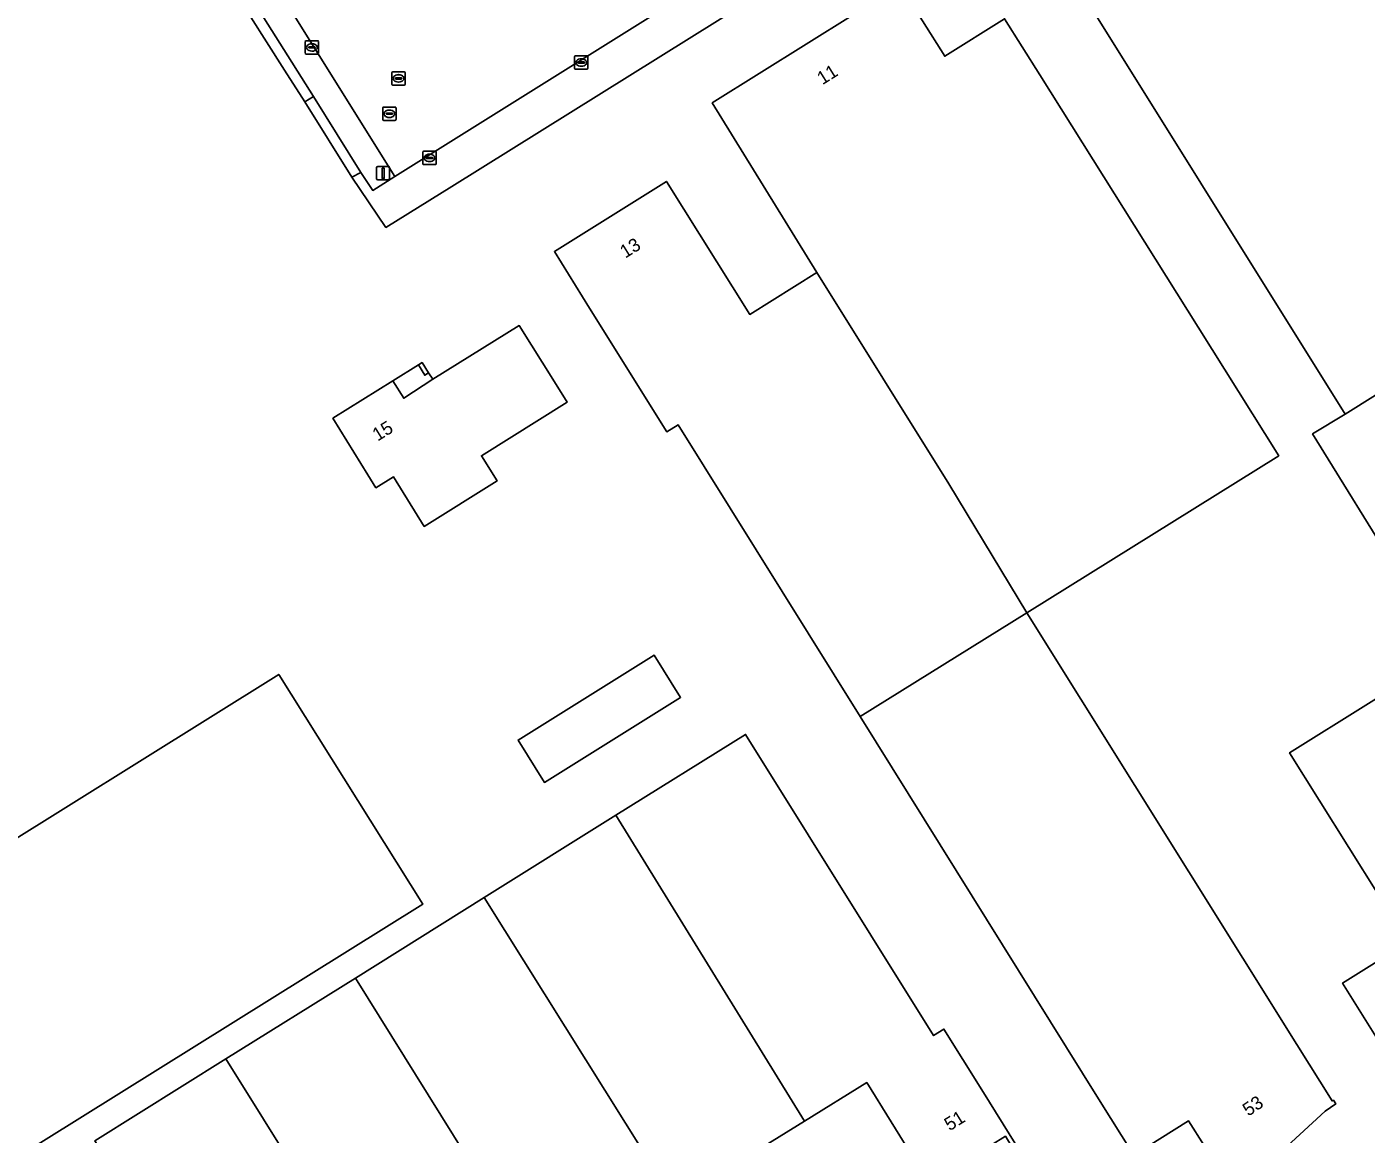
# Model space of a CAD drawing. Extents: x 158455 to 159797, y 387218 to 388672.
# Drawn here: x 158762.6 to 158863.3, y 387547.3 to 387630.6 of the extents above; entities that cross this region are included whole.
import ezdxf

# ---------------------------------------------------------------- set-up
doc = ezdxf.new("R2010")
doc.units = 0
for name, color, linetype in [('IMGEO_Erf', 7, 'Continuous'), ('IMGEO_Kolk', 7, 'Continuous'), ('IMGEO_Lichtmast', 7, 'Continuous'), ('IMGEO_Pand', 7, 'Continuous'), ('IMGEO_Pand_nummerreeks', 7, 'Continuous'), ('IMGEO_Pand_overbouw', 7, 'Continuous'), ('IMGEO_Parkeervlak_open', 7, 'Continuous'), ('IMGEO_Rijbaan_lokaal_gesloten', 7, 'Continuous'), ('IMGEO_Rioolput', 7, 'Continuous'), ('IMGEO_Voetpad_open', 7, 'Continuous')]:
    doc.layers.add(name, color=color, linetype=linetype)

msp = doc.modelspace()

# ---------------------------------------------------------------- linework, layer by layer
at = {"layer": 'IMGEO_Erf'}
for points in [[(158889.01, 387677.48), (158884.01, 387674.38), (158883.61, 387674.15), (158859.38, 387659.05), (158794.53, 387618.61), (158789.58, 387615.53), (158787.01, 387619.31), (158783.47, 387624.97), (158781.95, 387627.37), (158778.07, 387633.49), (158774.81, 387638.72), (158774.07, 387639.84), (158771.48, 387643.74), (158771, 387644.55), (158768.06, 387649.31), (158764.23, 387655.43), (158760.94, 387660.62)], [(158872.38, 387578.84), (158859.3, 387600), (158861.74, 387601.5), (158840.04, 387636.27), (158838.76, 387635.47), (158836.59, 387638.95), (158839.14, 387640.53), (158841.29, 387637.04), (158853.02, 387644.37), (158857.4, 387643.35), (158860.05, 387639.12), (158870.01, 387623.18)], [(158852.31, 387544.64), (158849.96, 387548.35), (158845.85, 387545.77), (158843.2, 387550.01), (158825.26, 387578.75), (158811.57, 387600.68), (158810.71, 387600.16), (158804.9, 387609.47), (158802.26, 387613.71), (158810.68, 387618.99), (158816.95, 387608.99), (158822, 387612.15), (158814.13, 387624.9), (158828.27, 387633.76), (158831.63, 387628.41), (158836.13, 387631.23), (158838.79, 387627), (158850.69, 387608.02), (158856.75, 387598.36), (158837.81, 387586.56), (158858.11, 387554.08), (158860.77, 387549.84), (158860.87, 387549.89), (158861.04, 387549.62), (158860.25, 387549.08), (158854.2, 387543.5)], [(158767.69, 387546.85), (158777.54, 387553), (158787.28, 387559.08), (158796.96, 387565.13), (158806.88, 387571.32), (158816.64, 387577.41), (158830.79, 387554.76), (158831.56, 387555.24), (158834.41, 387550.67), (158837.05, 387546.43)], [(158829.43, 387545.32), (158825.76, 387551.22), (158821.08, 387548.33), (158816.4, 387545.43)]]:
    msp.add_lwpolyline(points, dxfattribs=at)
for points in [[(158792.47, 387593.05), (158790.14, 387596.78), (158788.83, 387595.96), (158788.22, 387596.93), (158785.59, 387601.18), (158790.11, 387604), (158790.92, 387602.68), (158793.11, 387604.11), (158799.61, 387608.15), (158802.26, 387603.91), (158803.21, 387602.39), (158796.76, 387598.36), (158797.94, 387596.47)], [(158792.02, 387605.19), (158792.3, 387605.37), (158792.78, 387604.6), (158792.5, 387604.42)], [(158801.51, 387573.8), (158799.52, 387576.98), (158809.76, 387583.37), (158811.75, 387580.19)], [(158876.85, 387556.04), (158876.4, 387556.77), (158866.58, 387550.64), (158863.94, 387554.88), (158861.55, 387558.7), (158866.48, 387561.77), (158857.57, 387576.03), (158869.44, 387583.44), (158881.2, 387564.63), (158883.85, 387560.39)], [(158749.52, 387537.93), (158738.74, 387555.23), (158752.11, 387563.62), (158751.52, 387564.59), (158754.72, 387566.61), (158755.39, 387565.62), (158781.52, 387581.92), (158792.35, 387564.63)]]:
    msp.add_lwpolyline(points, close=True, dxfattribs=at)
at = {"layer": 'IMGEO_Kolk'}
for p, q in [((158783.51, 387628.65), (158783.51, 387629.5)), ((158783.58, 387629.57), (158784.44, 387629.57)), ((158784.51, 387629.5), (158784.51, 387628.65)), ((158784.44, 387628.57), (158783.58, 387628.57)), ((158783.77, 387629.07), (158783.77, 387629.08)), ((158783.81, 387629.12), (158784.21, 387629.12)), ((158784.21, 387629.03), (158783.81, 387629.03)), ((158784, 387629.35), (158784.02, 387629.35)), ((158784.02, 387628.79), (158784, 387628.79)), ((158784.25, 387629.08), (158784.25, 387629.07)), ((158803.85, 387628.44), (158804.7, 387628.44)), ((158803.77, 387627.51), (158803.77, 387628.36)), ((158804.7, 387627.43), (158803.85, 387627.43)), ((158804.03, 387627.93), (158804.03, 387627.94)), ((158804.47, 387627.89), (158804.07, 387627.89)), ((158804.08, 387627.98), (158804.47, 387627.98)), ((158804.26, 387628.21), (158804.29, 387628.21)), ((158804.28, 387627.66), (158804.26, 387627.66)), ((158804.52, 387627.94), (158804.52, 387627.93)), ((158804.78, 387628.36), (158804.78, 387627.51)), ((158792.36, 387620.33), (158792.36, 387621.18)), ((158792.43, 387621.26), (158793.29, 387621.26)), ((158792.62, 387620.75), (158792.62, 387620.76)), ((158792.66, 387620.8), (158793.06, 387620.8)), ((158793.06, 387620.71), (158792.66, 387620.71)), ((158792.87, 387620.48), (158792.84, 387620.48)), ((158792.85, 387621.04), (158792.87, 387621.04)), ((158793.1, 387620.76), (158793.1, 387620.75)), ((158793.36, 387621.18), (158793.36, 387620.33)), ((158793.29, 387620.26), (158792.43, 387620.26))]:
    msp.add_line(p, q, dxfattribs=at)
for points in [[(158783.51, 387628.65), (158783.51, 387629.5)], [(158783.58, 387629.57), (158784.44, 387629.57)], [(158784.51, 387629.5), (158784.51, 387628.65)], [(158784.44, 387628.57), (158783.58, 387628.57)], [(158803.85, 387628.44), (158804.7, 387628.44)], [(158803.77, 387627.51), (158803.77, 387628.36)], [(158804.7, 387627.43), (158803.85, 387627.43)], [(158804.78, 387628.36), (158804.78, 387627.51)], [(158792.36, 387620.33), (158792.36, 387621.18)], [(158792.43, 387621.26), (158793.29, 387621.26)], [(158793.36, 387621.18), (158793.36, 387620.33)], [(158793.29, 387620.26), (158792.43, 387620.26)]]:
    msp.add_lwpolyline(points, dxfattribs=at)
for centre, radius, start, end in [((158783.59, 387629.5), 0.0765, 91.552, 178.448), ((158783.59, 387629.5), 0.0765, 91.552, 178.448), ((158784.43, 387629.5), 0.0765, 1.552, 88.448), ((158784.43, 387629.5), 0.0765, 1.552, 88.448), ((158783.59, 387628.65), 0.0765, 181.552, 268.448), ((158783.59, 387628.65), 0.0765, 181.552, 268.448), ((158783.81, 387629.08), 0.0403, 85.8775, 175.7526), ((158783.81, 387629.07), 0.0366, 178.938, 274.7102), ((158784.21, 387629.08), 0.0386, 1.7309, 96.639), ((158784.21, 387629.07), 0.043, 264.8664, 352.4533), ((158784.43, 387628.65), 0.0765, 271.552, 358.448), ((158784.43, 387628.65), 0.0765, 271.552, 358.448), ((158803.85, 387628.36), 0.0765, 91.552, 178.448), ((158803.85, 387628.36), 0.0765, 91.552, 178.448), ((158804.7, 387628.36), 0.0765, 1.552, 88.448), ((158804.7, 387628.36), 0.0765, 1.552, 88.448), ((158803.85, 387627.51), 0.0765, 181.552, 268.448), ((158803.85, 387627.51), 0.0765, 181.552, 268.448), ((158804.07, 387627.94), 0.0403, 85.8775, 175.7526), ((158804.07, 387627.93), 0.0366, 178.938, 274.7102), ((158804.48, 387627.94), 0.0386, 1.7309, 96.639), ((158804.47, 387627.93), 0.043, 264.8664, 352.4533), ((158804.7, 387627.51), 0.0765, 271.552, 358.448), ((158804.7, 387627.51), 0.0765, 271.552, 358.448), ((158792.44, 387621.18), 0.0765, 91.552, 178.448), ((158792.44, 387621.18), 0.0765, 91.552, 178.448), ((158792.44, 387620.33), 0.0765, 181.552, 268.448), ((158792.44, 387620.33), 0.0765, 181.552, 268.448), ((158792.66, 387620.76), 0.0403, 85.8775, 175.7526), ((158792.65, 387620.75), 0.0366, 178.938, 274.7102), ((158793.06, 387620.76), 0.0386, 1.7309, 96.639), ((158793.06, 387620.76), 0.043, 264.8664, 352.4533), ((158793.28, 387621.18), 0.0765, 1.552, 88.448), ((158793.28, 387621.18), 0.0765, 1.552, 88.448), ((158793.28, 387620.33), 0.0765, 271.552, 358.448), ((158793.28, 387620.33), 0.0765, 271.552, 358.448)]:
    msp.add_arc(centre, radius, start, end, dxfattribs=at)
for centre, major_axis, ratio, start_param, end_param in [((158784, 387629.07), (-0.387, 0.002), 0.722429, 4.712389, 7.853982), ((158784.02, 387629.07), (-0.39, 0.002), 0.717154, 1.570796, 4.712389), ((158804.26, 387627.93), (-0.387, 0.002), 0.722429, 4.712389, 7.853982), ((158804.29, 387627.93), (-0.39, 0.002), 0.717154, 1.570796, 4.712389), ((158792.85, 387620.76), (-0.387, 0.002), 0.722429, 4.712389, 7.853982), ((158792.87, 387620.76), (-0.39, 0.002), 0.717154, 1.570796, 4.712389)]:
    msp.add_ellipse(centre, major_axis=major_axis, ratio=ratio, start_param=start_param, end_param=end_param, dxfattribs=at)
at = {"layer": 'IMGEO_Lichtmast'}
for p, q in [((158788.88, 387619.21), (158788.88, 387620.01)), ((158788.88, 387620.01), (158788.88, 387619.21)), ((158788.98, 387620.11), (158789.76, 387620.11)), ((158789.76, 387620.11), (158788.98, 387620.11)), ((158789.86, 387620.01), (158789.86, 387619.21)), ((158789.86, 387619.21), (158789.86, 387620.01)), ((158789.76, 387619.11), (158788.98, 387619.11)), ((158788.98, 387619.11), (158789.76, 387619.11))]:
    msp.add_line(p, q, dxfattribs=at)
msp.add_lwpolyline([(158789.29, 387619.98), (158789.45, 387619.98), (158789.45, 387619.23), (158789.29, 387619.23), (158789.29, 387619.98)], dxfattribs=at)
for centre, start, end in [((158788.98, 387620.01), 90, 180), ((158788.98, 387620.01), 90, 180), ((158789.76, 387620.01), 0, 90), ((158789.76, 387620.01), 360, 90), ((158788.98, 387619.21), 180, 270), ((158788.98, 387619.21), 180, 270), ((158789.76, 387619.21), 270, 0), ((158789.76, 387619.21), 270, 0)]:
    msp.add_arc(centre, 0.1, start, end, dxfattribs=at)
at = {"layer": 'IMGEO_Pand'}
for points in [[(158841.29, 387637.04), (158840.04, 387636.27), (158861.74, 387601.5), (158881.22, 387613.66), (158873.83, 387625.55), (158870.01, 387623.18), (158860.05, 387639.12), (158857.4, 387643.35), (158853.02, 387644.37)], [(158838.79, 387627), (158836.13, 387631.23), (158831.63, 387628.41), (158828.27, 387633.76), (158814.13, 387624.9), (158822, 387612.15), (158831.93, 387596.26), (158837.81, 387586.56), (158856.75, 387598.36), (158850.69, 387608.02)], [(158837.81, 387586.56), (158831.93, 387596.26), (158822, 387612.15), (158816.95, 387608.99), (158810.68, 387618.99), (158802.26, 387613.71), (158804.9, 387609.47), (158810.71, 387600.16), (158811.57, 387600.68), (158825.26, 387578.75)], [(158900.88, 387588.61), (158891.47, 387606.14), (158885.81, 387616.52), (158881.22, 387613.66), (158861.74, 387601.5), (158859.3, 387600), (158872.38, 387578.84), (158876.68, 387581.15), (158881.35, 387572.45), (158890.96, 387577.61), (158894.66, 387570.74), (158903.82, 387575.66), (158900.12, 387582.56), (158903.24, 387584.21)], [(158790.92, 387602.68), (158790.11, 387604), (158785.59, 387601.18), (158788.22, 387596.93), (158788.83, 387595.96), (158790.14, 387596.78), (158792.47, 387593.05), (158797.94, 387596.47), (158796.76, 387598.36), (158803.21, 387602.39), (158802.26, 387603.91), (158799.61, 387608.15), (158793.11, 387604.11)], [(158792.02, 387605.19), (158792.5, 387604.42), (158792.78, 387604.6), (158792.3, 387605.37)], [(158837.81, 387586.56), (158825.26, 387578.75), (158843.2, 387550.01), (158845.85, 387545.77), (158849.96, 387548.35), (158852.31, 387544.64), (158852.19, 387544.46), (158852.34, 387544.19), (158853.15, 387544.67), (158854.2, 387543.5), (158860.25, 387549.08), (158861.04, 387549.62), (158860.87, 387549.89), (158860.77, 387549.84), (158858.11, 387554.08)], [(158799.52, 387576.98), (158801.51, 387573.8), (158811.75, 387580.19), (158809.76, 387583.37)], [(158883.85, 387560.39), (158881.2, 387564.63), (158869.44, 387583.44), (158857.57, 387576.03), (158866.48, 387561.77), (158861.55, 387558.7), (158863.94, 387554.88), (158866.58, 387550.64), (158876.4, 387556.77), (158876.85, 387556.04)], [(158749.52, 387537.93), (158792.35, 387564.63), (158781.52, 387581.92), (158755.39, 387565.62), (158754.72, 387566.61), (158751.52, 387564.59), (158752.11, 387563.62), (158738.74, 387555.23)], [(158806.88, 387571.32), (158821.08, 387548.33), (158825.76, 387551.22), (158829.43, 387545.32), (158830.62, 387546.05), (158831.67, 387544.38), (158836.19, 387547.19), (158836.77, 387546.25), (158837.05, 387546.43), (158834.41, 387550.67), (158831.56, 387555.24), (158830.79, 387554.76), (158816.64, 387577.41)], [(158806.88, 387571.32), (158796.96, 387565.13), (158813.7, 387538.43), (158817.6, 387540.87), (158816.55, 387542.56), (158817.72, 387543.3), (158816.4, 387545.43), (158821.08, 387548.33)], [(158799.18, 387539.99), (158803.85, 387542.91), (158807.56, 387536.97), (158808.76, 387537.7), (158809.81, 387535.99), (158813.7, 387538.43), (158796.96, 387565.13), (158787.28, 387559.08)], [(158799.18, 387539.99), (158787.28, 387559.08), (158777.54, 387553), (158791.82, 387530.11), (158795.72, 387532.55), (158794.66, 387534.23), (158795.84, 387534.97), (158794.52, 387537.08)], [(158777.54, 387553), (158767.69, 387546.85), (158777.26, 387531.66), (158781.92, 387534.6), (158785.66, 387528.63), (158786.85, 387529.37), (158787.91, 387527.67), (158791.82, 387530.11)]]:
    msp.add_lwpolyline(points, close=True, dxfattribs=at)
at = {"layer": 'IMGEO_Pand_overbouw'}
msp.add_lwpolyline([(158790.11, 387604), (158790.92, 387602.68), (158793.11, 387604.11), (158792.78, 387604.6), (158792.5, 387604.42), (158792.02, 387605.19)], close=True, dxfattribs=at)
at = {"layer": 'IMGEO_Parkeervlak_open'}
msp.add_lwpolyline([(158717.45, 387734.72), (158717.06, 387732.93), (158717.11, 387732.49), (158719.65, 387728.42), (158722.99, 387723.1), (158732.01, 387708.73), (158738.06, 387699.04), (158746.82, 387685.02), (158753.27, 387674.73), (158761.73, 387661.12), (158765, 387655.89), (158768.84, 387649.81), (158771.86, 387645.04), (158771, 387644.55), (158771.48, 387643.74), (158772.29, 387644.26), (158775.48, 387639.14), (158778.76, 387633.9), (158784.13, 387625.39), (158787.69, 387619.67), (158788.59, 387618.31), (158790.26, 387619.35), (158782.56, 387631.67), (158717.38, 387735.85)], dxfattribs=at)
at = {"layer": 'IMGEO_Rijbaan_lokaal_gesloten'}
msp.add_lwpolyline([(158789.3, 387636.07), (158782.56, 387631.67), (158790.26, 387619.35), (158883.63, 387677.73), (158887.24, 387680.02), (158907.51, 387692.65)], dxfattribs=at)
at = {"layer": 'IMGEO_Rioolput'}
for p, q in [((158790.03, 387626.31), (158790.03, 387627.16)), ((158790.11, 387627.24), (158790.96, 387627.24)), ((158790.29, 387626.73), (158790.29, 387626.74)), ((158790.33, 387626.78), (158790.73, 387626.78)), ((158790.73, 387626.69), (158790.33, 387626.69)), ((158790.52, 387627.02), (158790.54, 387627.02)), ((158790.54, 387626.46), (158790.52, 387626.46)), ((158790.77, 387626.74), (158790.77, 387626.73)), ((158791.03, 387627.16), (158791.03, 387626.31)), ((158790.96, 387626.24), (158790.11, 387626.24)), ((158789.34, 387623.66), (158789.34, 387624.51)), ((158789.41, 387624.58), (158790.27, 387624.58)), ((158789.83, 387624.36), (158789.85, 387624.36)), ((158790.34, 387624.51), (158790.34, 387623.66)), ((158790.27, 387623.58), (158789.41, 387623.58)), ((158789.6, 387624.08), (158789.6, 387624.09)), ((158789.64, 387624.13), (158790.04, 387624.13)), ((158790.04, 387624.04), (158789.64, 387624.04)), ((158789.85, 387623.8), (158789.83, 387623.8)), ((158790.08, 387624.09), (158790.08, 387624.08))]:
    msp.add_line(p, q, dxfattribs=at)
for points in [[(158790.03, 387626.31), (158790.03, 387627.16)], [(158790.11, 387627.24), (158790.96, 387627.24)], [(158791.03, 387627.16), (158791.03, 387626.31)], [(158790.96, 387626.24), (158790.11, 387626.24)], [(158789.34, 387623.66), (158789.34, 387624.51)], [(158789.41, 387624.58), (158790.27, 387624.58)], [(158790.34, 387624.51), (158790.34, 387623.66)], [(158790.27, 387623.58), (158789.41, 387623.58)]]:
    msp.add_lwpolyline(points, dxfattribs=at)
for centre, radius, start, end in [((158790.11, 387627.16), 0.0765, 91.552, 178.448), ((158790.11, 387627.16), 0.0765, 91.552, 178.448), ((158790.33, 387626.74), 0.0403, 85.8775, 175.7526), ((158790.33, 387626.73), 0.0366, 178.938, 274.7102), ((158790.74, 387626.74), 0.0386, 1.7309, 96.639), ((158790.73, 387626.74), 0.043, 264.8664, 352.4533), ((158790.96, 387627.16), 0.0765, 1.552, 88.448), ((158790.96, 387627.16), 0.0765, 1.552, 88.448), ((158790.11, 387626.31), 0.0765, 181.552, 268.448), ((158790.11, 387626.31), 0.0765, 181.552, 268.448), ((158790.96, 387626.31), 0.0765, 271.552, 358.448), ((158790.96, 387626.31), 0.0765, 271.552, 358.448), ((158789.42, 387624.51), 0.0765, 91.552, 178.448), ((158789.42, 387624.51), 0.0765, 91.552, 178.448), ((158790.26, 387624.51), 0.0765, 1.552, 88.448), ((158790.26, 387624.51), 0.0765, 1.552, 88.448), ((158789.42, 387623.66), 0.0765, 181.552, 268.448), ((158789.42, 387623.66), 0.0765, 181.552, 268.448), ((158789.64, 387624.09), 0.0403, 85.8775, 175.7526), ((158789.64, 387624.08), 0.0366, 178.938, 274.7102), ((158790.04, 387624.09), 0.0386, 1.7309, 96.639), ((158790.04, 387624.08), 0.043, 264.8664, 352.4533), ((158790.26, 387623.66), 0.0765, 271.552, 358.448), ((158790.26, 387623.66), 0.0765, 271.552, 358.448)]:
    msp.add_arc(centre, radius, start, end, dxfattribs=at)
for centre, major_axis, ratio, start_param, end_param in [((158790.52, 387626.74), (-0.387, 0.002), 0.722429, 4.712389, 7.853982), ((158790.54, 387626.74), (-0.39, 0.002), 0.717154, 1.570796, 4.712389), ((158789.83, 387624.08), (-0.387, 0.002), 0.722429, 4.712389, 7.853982), ((158789.85, 387624.08), (-0.39, 0.002), 0.717154, 1.570796, 4.712389)]:
    msp.add_ellipse(centre, major_axis=major_axis, ratio=ratio, start_param=start_param, end_param=end_param, dxfattribs=at)
at = {"layer": 'IMGEO_Voetpad_open'}
msp.add_lwpolyline([(158883.63, 387677.73), (158790.26, 387619.35), (158788.59, 387618.31), (158787.69, 387619.67), (158787.01, 387619.31), (158789.58, 387615.53), (158794.53, 387618.61), (158859.38, 387659.05), (158883.61, 387674.15), (158883.07, 387674.98)], dxfattribs=at)
for points in [[(158778.76, 387633.9), (158778.07, 387633.49), (158781.95, 387627.37), (158783.47, 387624.97), (158784.13, 387625.39)], [(158787.01, 387619.31), (158787.69, 387619.67), (158784.13, 387625.39), (158783.47, 387624.97)]]:
    msp.add_lwpolyline(points, close=True, dxfattribs=at)

# ---------------------------------------------------------------- texts
at = {"layer": 'IMGEO_Pand_nummerreeks'}
for s, rotation, p in [('11', 32.0914, (158822.42, 387626.22)), ('13', 32.0585, (158807.59, 387613.18)), ('15', 31.9016, (158788.96, 387599.42)), ('53', 33.8389, (158854.46, 387548.65)), ('51', 31.8892, (158831.99, 387547.55))]:
    msp.add_text(s, height=1, rotation=rotation, dxfattribs=at).set_placement(p)

doc.saveas('drawing.dxf')
